(* Logix 5000 project; controller Electronic_Displays vendor 1 type 14 code 65 rev 17.4; software revision 17.01; part 5 of 9 *)
(* tags used below, declared in another part *)
   ENText2Message : BOOL;   // 0 = don't sent message 1 = send message
   ENText3Message : BOOL;   // 0 = don't sent message 1 = send message
   ENText4Message : BOOL;   // 0 = don't sent message 1 = send message
   ENTextFormats : BOOL;   // 0 = no additional text formatting 1 = enable text formatting
   ENVariable2Message : BOOL;   // 0 = don't sent embedded variable 1 = send embedded variable
   ENVariable3Message : BOOL;   // 0 = don't sent embedded variable 1 = send embedded variable
   ENVariable4Message : BOOL;   // 0 = don't sent embedded variable 1 = send embedded variable
   ENVariableFormats : BOOL;   // 0 = no additional text formatting 1 = enable text formatting
   SEQ : DINT;   // Sequence Number
   InCycle : BOOL;   // Incycle
   SignColor : STRING;
   SignFont : STRING;
   Packet : STRING[7];   // Packet Array to send to sign
   SignTextMessage4 : STRING;
   SignTextMessage3 : STRING;
   SignTextMessage2 : STRING;
   SignNextLine : STRING;   // DO NOT EDIT = ^M
   SignVariableFont : STRING;
   SignVariableColor : STRING;
   SignVariable3 : STRING;
   SignVariable2 : STRING;
   Select : DINT;   // Packet Array Select
   TotalPacketCount : DINT[7];   // Total Character Count
   PacketMax : DINT;   // Max Packet Count
   SignAttribute : STRING;
   SignVariableAttribute : STRING;
(* SendSignMessage, continued *)

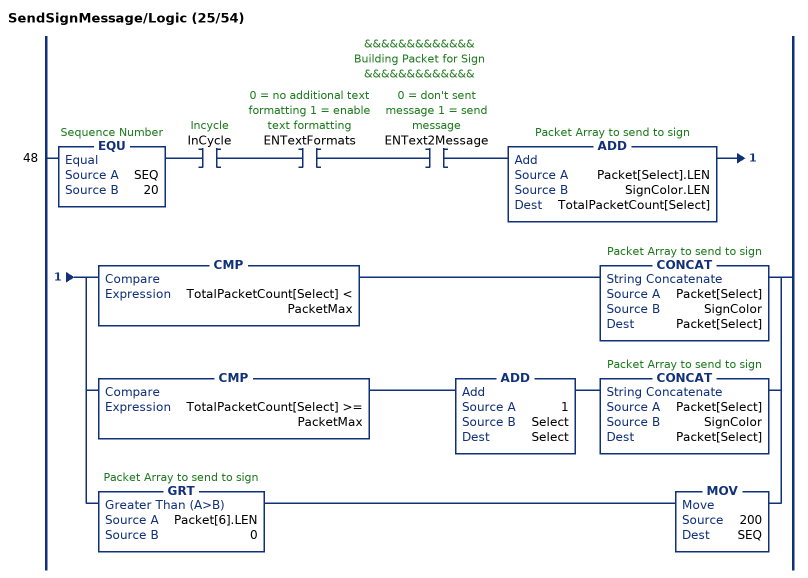
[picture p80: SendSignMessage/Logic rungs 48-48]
   // &&&&&&&&&&&&&
   // Building Packet for Sign
   // &&&&&&&&&&&&&
   48: EQU(SEQ,20)XIC(InCycle)XIC(ENTextFormats)XIC(ENText2Message)ADD(Packet[Select].LEN,SignColor.LEN,TotalPacketCount[Select])[CMP(TotalPacketCount[Select] < PacketMax) CONCAT(Packet[Select],SignColor,Packet[Select]) ,CMP(TotalPacketCount[Select] >= PacketMax) ADD(1,Select,Select) CONCAT(Packet[Select],SignColor,Packet[Select]) ,GRT(Packet[6].LEN,0) MOV(200,SEQ) ];
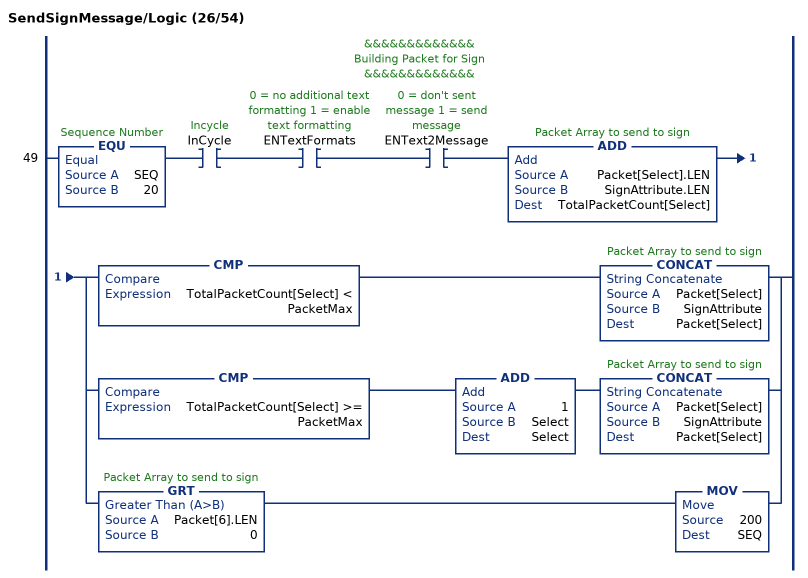
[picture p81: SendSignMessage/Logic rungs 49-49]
   // &&&&&&&&&&&&&
   // Building Packet for Sign
   // &&&&&&&&&&&&&
   49: EQU(SEQ,20)XIC(InCycle)XIC(ENTextFormats)XIC(ENText2Message)ADD(Packet[Select].LEN,SignAttribute.LEN,TotalPacketCount[Select])[CMP(TotalPacketCount[Select] < PacketMax) CONCAT(Packet[Select],SignAttribute,Packet[Select]) ,CMP(TotalPacketCount[Select] >= PacketMax) ADD(1,Select,Select) CONCAT(Packet[Select],SignAttribute,Packet[Select]) ,GRT(Packet[6].LEN,0) MOV(200,SEQ) ];
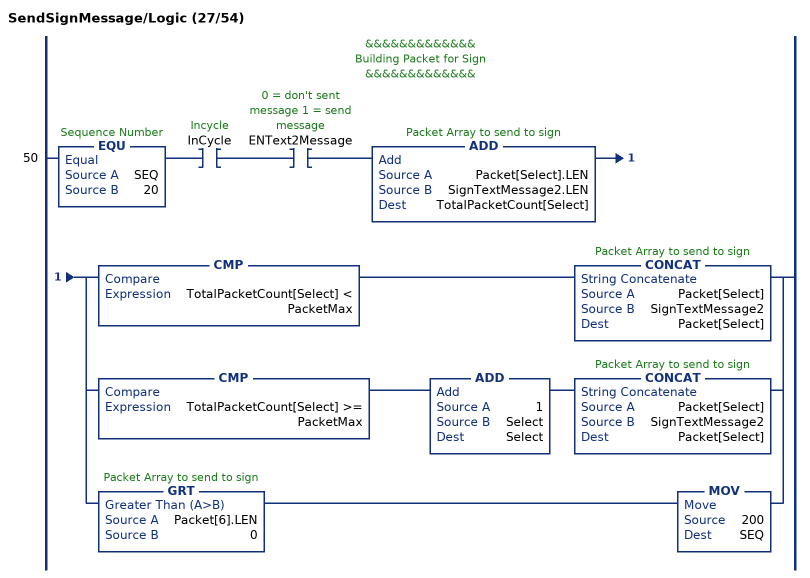
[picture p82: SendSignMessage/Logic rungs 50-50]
   // &&&&&&&&&&&&&
   // Building Packet for Sign
   // &&&&&&&&&&&&&
   50: EQU(SEQ,20)XIC(InCycle)XIC(ENText2Message)ADD(Packet[Select].LEN,SignTextMessage2.LEN,TotalPacketCount[Select])[CMP(TotalPacketCount[Select] < PacketMax) CONCAT(Packet[Select],SignTextMessage2,Packet[Select]) ,CMP(TotalPacketCount[Select] >= PacketMax) ADD(1,Select,Select) CONCAT(Packet[Select],SignTextMessage2,Packet[Select]) ,GRT(Packet[6].LEN,0) MOV(200,SEQ) ];
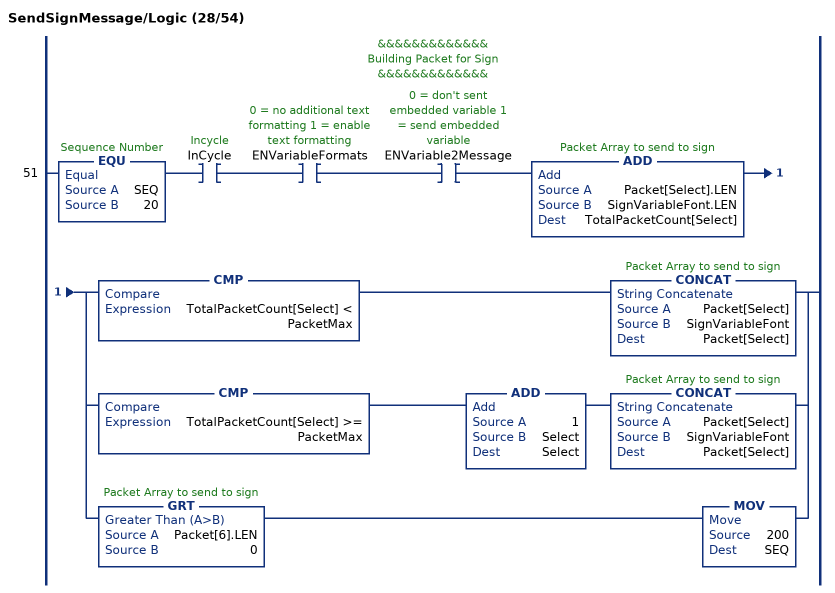
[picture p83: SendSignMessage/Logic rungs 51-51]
   // &&&&&&&&&&&&&
   // Building Packet for Sign
   // &&&&&&&&&&&&&
   51: EQU(SEQ,20)XIC(InCycle)XIC(ENVariableFormats)XIC(ENVariable2Message)ADD(Packet[Select].LEN,SignVariableFont.LEN,TotalPacketCount[Select])[CMP(TotalPacketCount[Select] < PacketMax) CONCAT(Packet[Select],SignVariableFont,Packet[Select]) ,CMP(TotalPacketCount[Select] >= PacketMax) ADD(1,Select,Select) CONCAT(Packet[Select],SignVariableFont,Packet[Select]) ,GRT(Packet[6].LEN,0) MOV(200,SEQ) ];
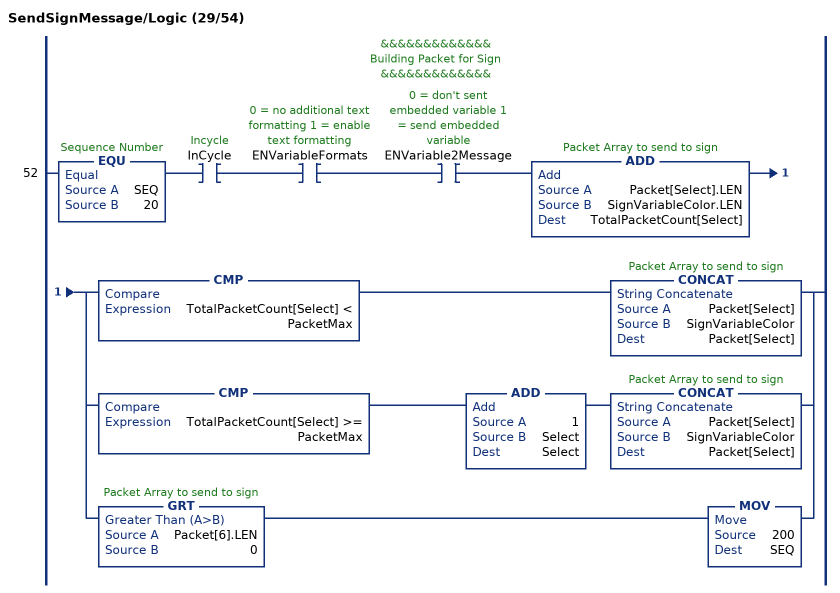
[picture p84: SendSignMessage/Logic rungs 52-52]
   // &&&&&&&&&&&&&
   // Building Packet for Sign
   // &&&&&&&&&&&&&
   52: EQU(SEQ,20)XIC(InCycle)XIC(ENVariableFormats)XIC(ENVariable2Message)ADD(Packet[Select].LEN,SignVariableColor.LEN,TotalPacketCount[Select])[CMP(TotalPacketCount[Select] < PacketMax) CONCAT(Packet[Select],SignVariableColor,Packet[Select]) ,CMP(TotalPacketCount[Select] >= PacketMax) ADD(1,Select,Select) CONCAT(Packet[Select],SignVariableColor,Packet[Select]) ,GRT(Packet[6].LEN,0) MOV(200,SEQ) ];
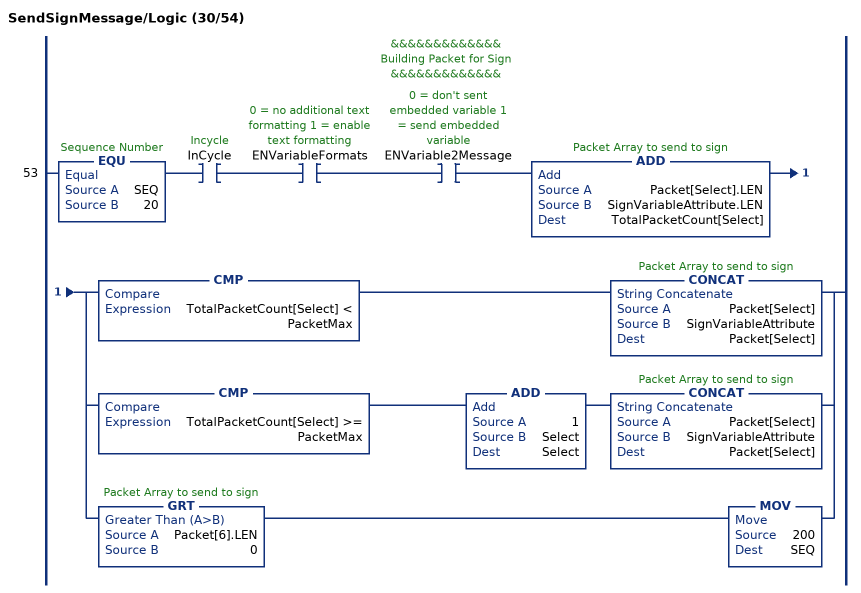
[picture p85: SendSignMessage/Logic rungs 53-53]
   // &&&&&&&&&&&&&
   // Building Packet for Sign
   // &&&&&&&&&&&&&
   53: EQU(SEQ,20)XIC(InCycle)XIC(ENVariableFormats)XIC(ENVariable2Message)ADD(Packet[Select].LEN,SignVariableAttribute.LEN,TotalPacketCount[Select])[CMP(TotalPacketCount[Select] < PacketMax) CONCAT(Packet[Select],SignVariableAttribute,Packet[Select]) ,CMP(TotalPacketCount[Select] >= PacketMax) ADD(1,Select,Select) CONCAT(Packet[Select],SignVariableAttribute,Packet[Select]) ,GRT(Packet[6].LEN,0) MOV(200,SEQ) ];
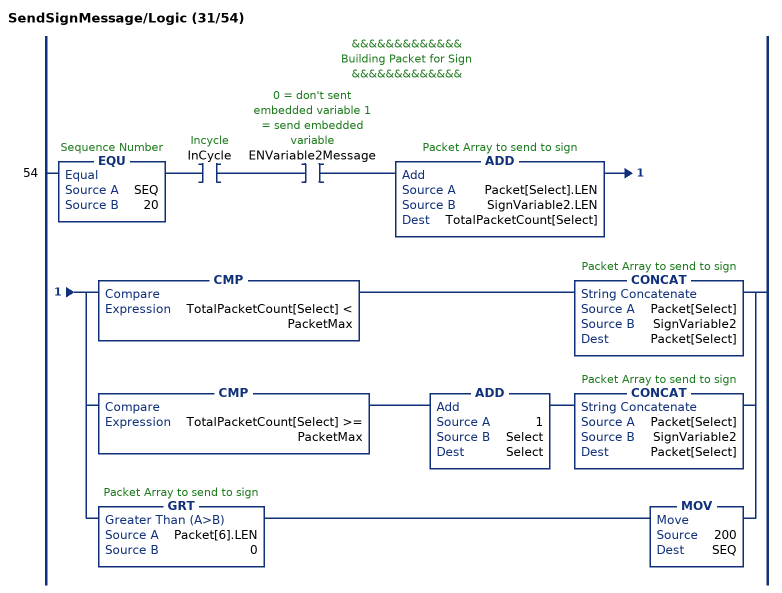
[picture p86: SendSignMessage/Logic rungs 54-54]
   // &&&&&&&&&&&&&
   // Building Packet for Sign
   // &&&&&&&&&&&&&
   54: EQU(SEQ,20)XIC(InCycle)XIC(ENVariable2Message)ADD(Packet[Select].LEN,SignVariable2.LEN,TotalPacketCount[Select])[CMP(TotalPacketCount[Select] < PacketMax) CONCAT(Packet[Select],SignVariable2,Packet[Select]) ,CMP(TotalPacketCount[Select] >= PacketMax) ADD(1,Select,Select) CONCAT(Packet[Select],SignVariable2,Packet[Select]) ,GRT(Packet[6].LEN,0) MOV(200,SEQ) ];
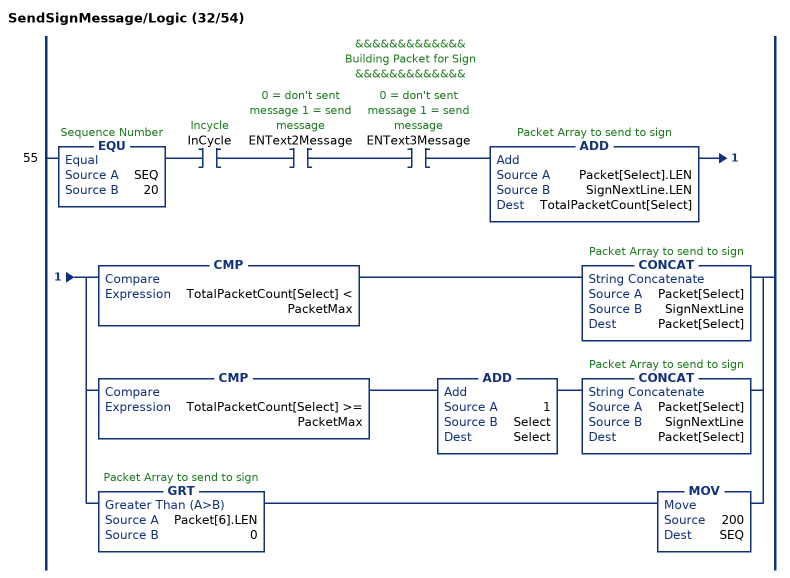
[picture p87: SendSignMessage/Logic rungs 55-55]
   // &&&&&&&&&&&&&
   // Building Packet for Sign
   // &&&&&&&&&&&&&
   55: EQU(SEQ,20)XIC(InCycle)XIC(ENText2Message)XIC(ENText3Message)ADD(Packet[Select].LEN,SignNextLine.LEN,TotalPacketCount[Select])[CMP(TotalPacketCount[Select] < PacketMax) CONCAT(Packet[Select],SignNextLine,Packet[Select]) ,CMP(TotalPacketCount[Select] >= PacketMax) ADD(1,Select,Select) CONCAT(Packet[Select],SignNextLine,Packet[Select]) ,GRT(Packet[6].LEN,0) MOV(200,SEQ) ];
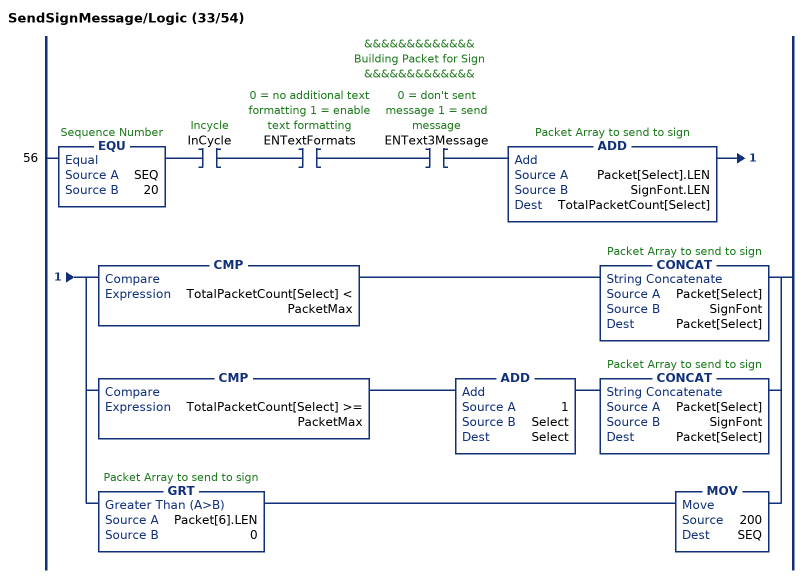
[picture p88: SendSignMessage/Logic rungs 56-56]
   // &&&&&&&&&&&&&
   // Building Packet for Sign
   // &&&&&&&&&&&&&
   56: EQU(SEQ,20)XIC(InCycle)XIC(ENTextFormats)XIC(ENText3Message)ADD(Packet[Select].LEN,SignFont.LEN,TotalPacketCount[Select])[CMP(TotalPacketCount[Select] < PacketMax) CONCAT(Packet[Select],SignFont,Packet[Select]) ,CMP(TotalPacketCount[Select] >= PacketMax) ADD(1,Select,Select) CONCAT(Packet[Select],SignFont,Packet[Select]) ,GRT(Packet[6].LEN,0) MOV(200,SEQ) ];
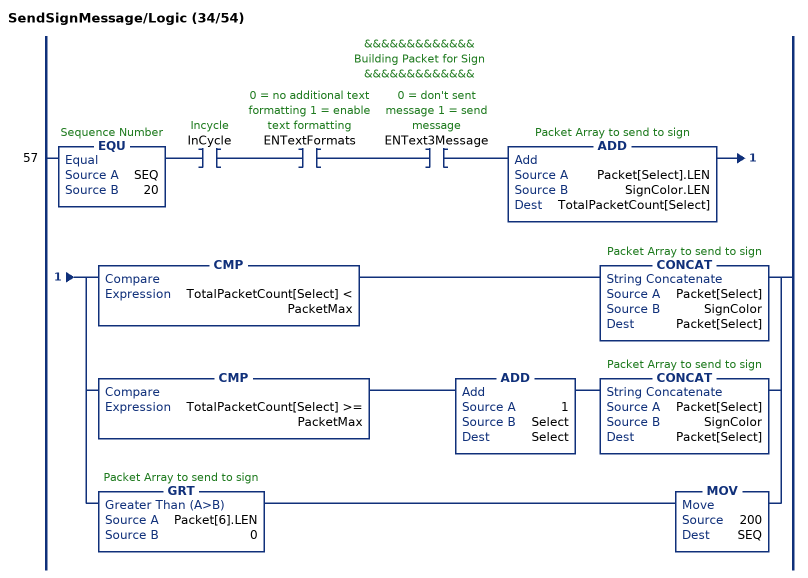
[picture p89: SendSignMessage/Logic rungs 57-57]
   // &&&&&&&&&&&&&
   // Building Packet for Sign
   // &&&&&&&&&&&&&
   57: EQU(SEQ,20)XIC(InCycle)XIC(ENTextFormats)XIC(ENText3Message)ADD(Packet[Select].LEN,SignColor.LEN,TotalPacketCount[Select])[CMP(TotalPacketCount[Select] < PacketMax) CONCAT(Packet[Select],SignColor,Packet[Select]) ,CMP(TotalPacketCount[Select] >= PacketMax) ADD(1,Select,Select) CONCAT(Packet[Select],SignColor,Packet[Select]) ,GRT(Packet[6].LEN,0) MOV(200,SEQ) ];
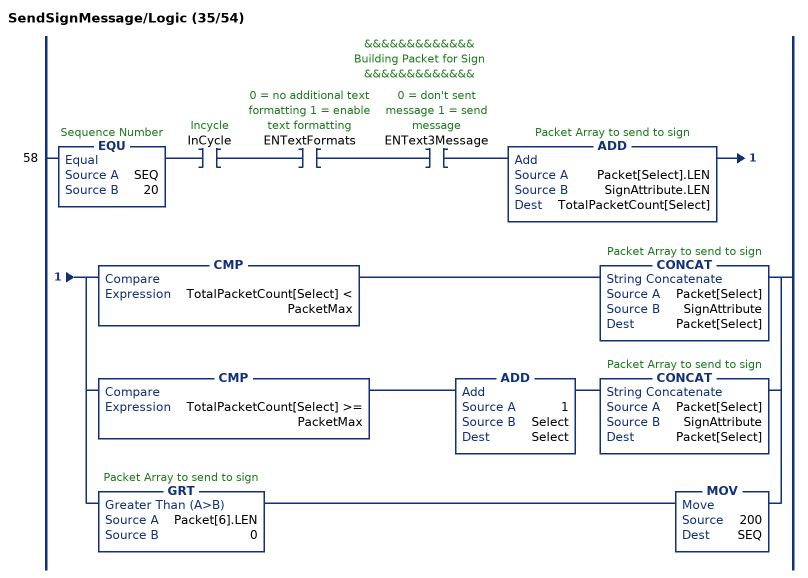
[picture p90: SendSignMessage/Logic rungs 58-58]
   // &&&&&&&&&&&&&
   // Building Packet for Sign
   // &&&&&&&&&&&&&
   58: EQU(SEQ,20)XIC(InCycle)XIC(ENTextFormats)XIC(ENText3Message)ADD(Packet[Select].LEN,SignAttribute.LEN,TotalPacketCount[Select])[CMP(TotalPacketCount[Select] < PacketMax) CONCAT(Packet[Select],SignAttribute,Packet[Select]) ,CMP(TotalPacketCount[Select] >= PacketMax) ADD(1,Select,Select) CONCAT(Packet[Select],SignAttribute,Packet[Select]) ,GRT(Packet[6].LEN,0) MOV(200,SEQ) ];
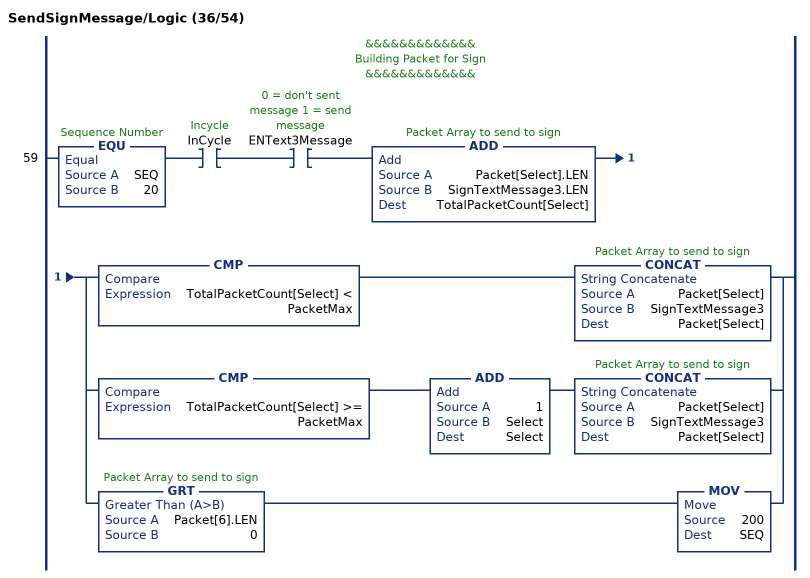
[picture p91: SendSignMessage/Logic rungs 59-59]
   // &&&&&&&&&&&&&
   // Building Packet for Sign
   // &&&&&&&&&&&&&
   59: EQU(SEQ,20)XIC(InCycle)XIC(ENText3Message)ADD(Packet[Select].LEN,SignTextMessage3.LEN,TotalPacketCount[Select])[CMP(TotalPacketCount[Select] < PacketMax) CONCAT(Packet[Select],SignTextMessage3,Packet[Select]) ,CMP(TotalPacketCount[Select] >= PacketMax) ADD(1,Select,Select) CONCAT(Packet[Select],SignTextMessage3,Packet[Select]) ,GRT(Packet[6].LEN,0) MOV(200,SEQ) ];
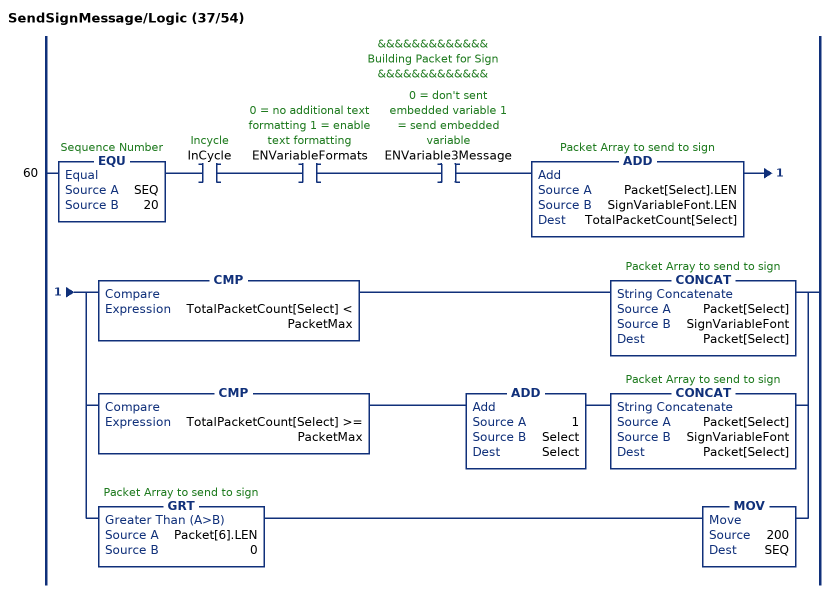
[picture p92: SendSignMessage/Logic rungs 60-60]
   // &&&&&&&&&&&&&
   // Building Packet for Sign
   // &&&&&&&&&&&&&
   60: EQU(SEQ,20)XIC(InCycle)XIC(ENVariableFormats)XIC(ENVariable3Message)ADD(Packet[Select].LEN,SignVariableFont.LEN,TotalPacketCount[Select])[CMP(TotalPacketCount[Select] < PacketMax) CONCAT(Packet[Select],SignVariableFont,Packet[Select]) ,CMP(TotalPacketCount[Select] >= PacketMax) ADD(1,Select,Select) CONCAT(Packet[Select],SignVariableFont,Packet[Select]) ,GRT(Packet[6].LEN,0) MOV(200,SEQ) ];
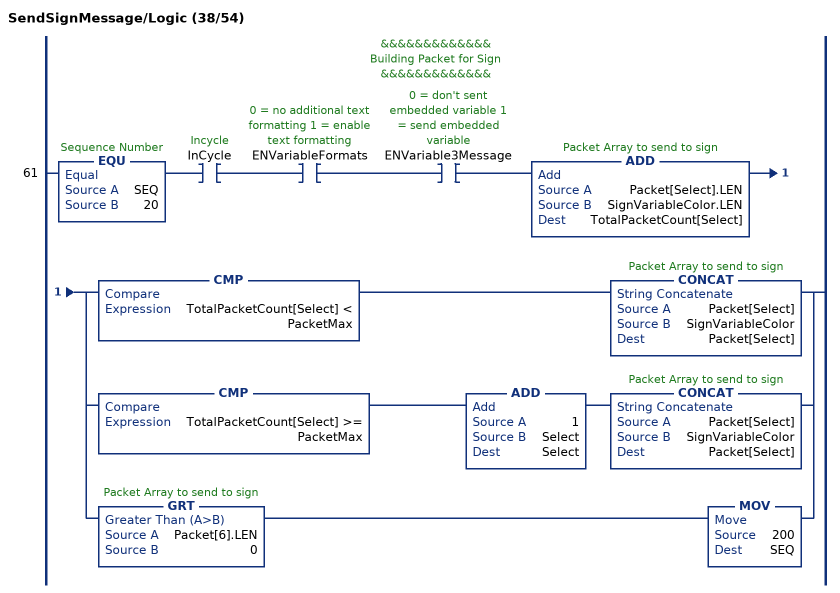
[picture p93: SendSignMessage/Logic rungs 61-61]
   // &&&&&&&&&&&&&
   // Building Packet for Sign
   // &&&&&&&&&&&&&
   61: EQU(SEQ,20)XIC(InCycle)XIC(ENVariableFormats)XIC(ENVariable3Message)ADD(Packet[Select].LEN,SignVariableColor.LEN,TotalPacketCount[Select])[CMP(TotalPacketCount[Select] < PacketMax) CONCAT(Packet[Select],SignVariableColor,Packet[Select]) ,CMP(TotalPacketCount[Select] >= PacketMax) ADD(1,Select,Select) CONCAT(Packet[Select],SignVariableColor,Packet[Select]) ,GRT(Packet[6].LEN,0) MOV(200,SEQ) ];
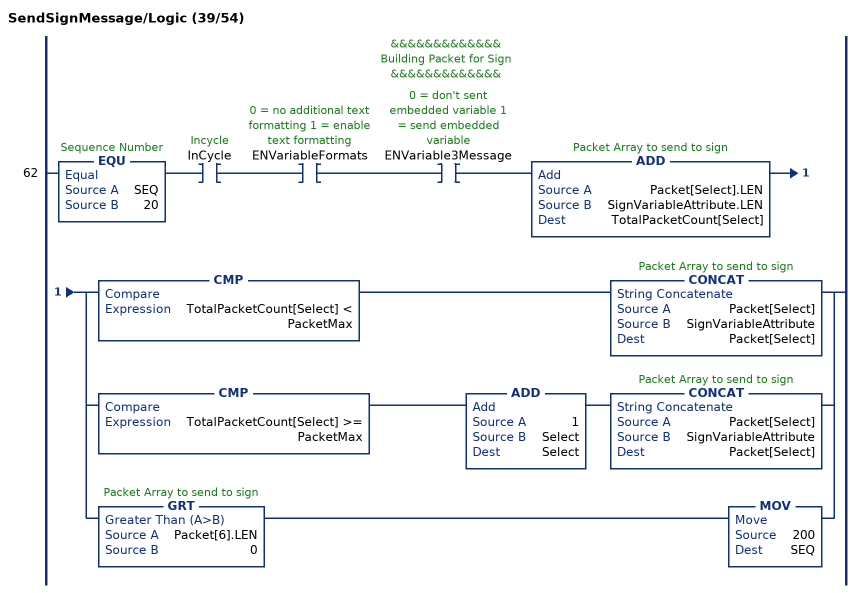
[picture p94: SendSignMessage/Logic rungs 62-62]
   // &&&&&&&&&&&&&
   // Building Packet for Sign
   // &&&&&&&&&&&&&
   62: EQU(SEQ,20)XIC(InCycle)XIC(ENVariableFormats)XIC(ENVariable3Message)ADD(Packet[Select].LEN,SignVariableAttribute.LEN,TotalPacketCount[Select])[CMP(TotalPacketCount[Select] < PacketMax) CONCAT(Packet[Select],SignVariableAttribute,Packet[Select]) ,CMP(TotalPacketCount[Select] >= PacketMax) ADD(1,Select,Select) CONCAT(Packet[Select],SignVariableAttribute,Packet[Select]) ,GRT(Packet[6].LEN,0) MOV(200,SEQ) ];
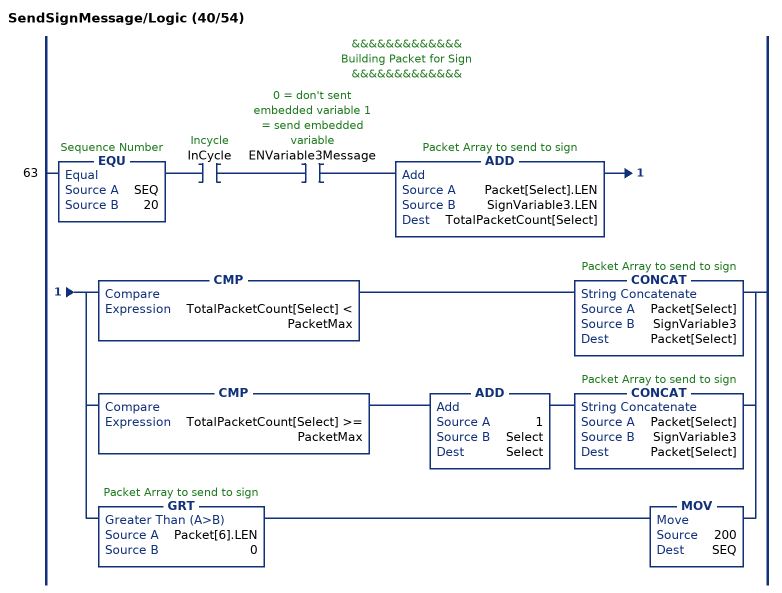
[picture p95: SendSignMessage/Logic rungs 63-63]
   // &&&&&&&&&&&&&
   // Building Packet for Sign
   // &&&&&&&&&&&&&
   63: EQU(SEQ,20)XIC(InCycle)XIC(ENVariable3Message)ADD(Packet[Select].LEN,SignVariable3.LEN,TotalPacketCount[Select])[CMP(TotalPacketCount[Select] < PacketMax) CONCAT(Packet[Select],SignVariable3,Packet[Select]) ,CMP(TotalPacketCount[Select] >= PacketMax) ADD(1,Select,Select) CONCAT(Packet[Select],SignVariable3,Packet[Select]) ,GRT(Packet[6].LEN,0) MOV(200,SEQ) ];
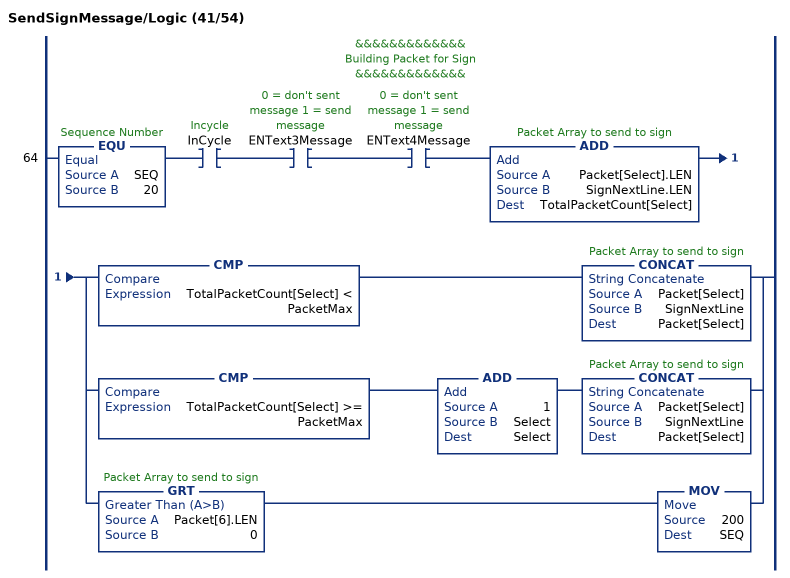
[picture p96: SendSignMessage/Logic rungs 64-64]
   // &&&&&&&&&&&&&
   // Building Packet for Sign
   // &&&&&&&&&&&&&
   64: EQU(SEQ,20)XIC(InCycle)XIC(ENText3Message)XIC(ENText4Message)ADD(Packet[Select].LEN,SignNextLine.LEN,TotalPacketCount[Select])[CMP(TotalPacketCount[Select] < PacketMax) CONCAT(Packet[Select],SignNextLine,Packet[Select]) ,CMP(TotalPacketCount[Select] >= PacketMax) ADD(1,Select,Select) CONCAT(Packet[Select],SignNextLine,Packet[Select]) ,GRT(Packet[6].LEN,0) MOV(200,SEQ) ];
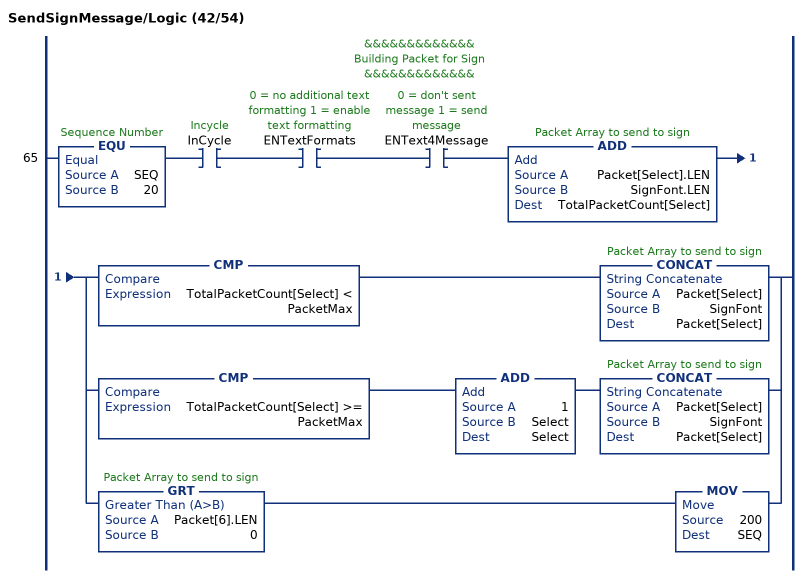
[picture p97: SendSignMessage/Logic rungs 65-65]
   // &&&&&&&&&&&&&
   // Building Packet for Sign
   // &&&&&&&&&&&&&
   65: EQU(SEQ,20)XIC(InCycle)XIC(ENTextFormats)XIC(ENText4Message)ADD(Packet[Select].LEN,SignFont.LEN,TotalPacketCount[Select])[CMP(TotalPacketCount[Select] < PacketMax) CONCAT(Packet[Select],SignFont,Packet[Select]) ,CMP(TotalPacketCount[Select] >= PacketMax) ADD(1,Select,Select) CONCAT(Packet[Select],SignFont,Packet[Select]) ,GRT(Packet[6].LEN,0) MOV(200,SEQ) ];
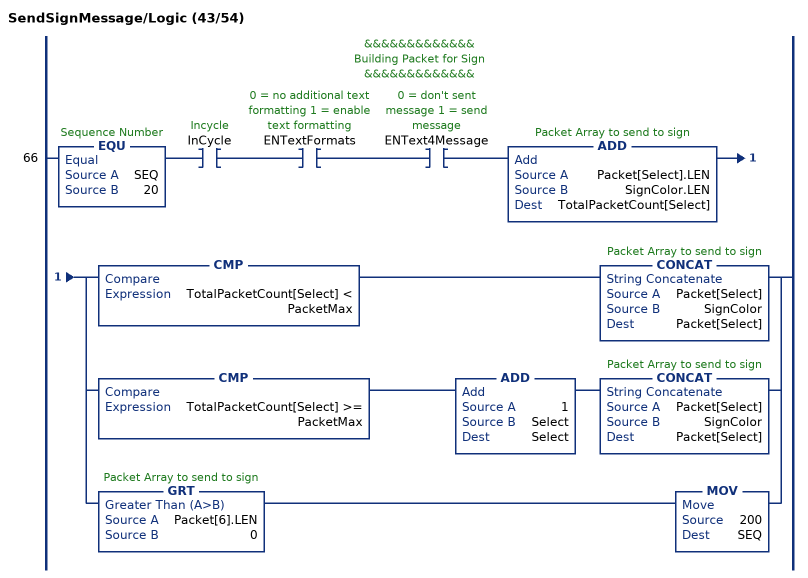
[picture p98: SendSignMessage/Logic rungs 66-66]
   // &&&&&&&&&&&&&
   // Building Packet for Sign
   // &&&&&&&&&&&&&
   66: EQU(SEQ,20)XIC(InCycle)XIC(ENTextFormats)XIC(ENText4Message)ADD(Packet[Select].LEN,SignColor.LEN,TotalPacketCount[Select])[CMP(TotalPacketCount[Select] < PacketMax) CONCAT(Packet[Select],SignColor,Packet[Select]) ,CMP(TotalPacketCount[Select] >= PacketMax) ADD(1,Select,Select) CONCAT(Packet[Select],SignColor,Packet[Select]) ,GRT(Packet[6].LEN,0) MOV(200,SEQ) ];
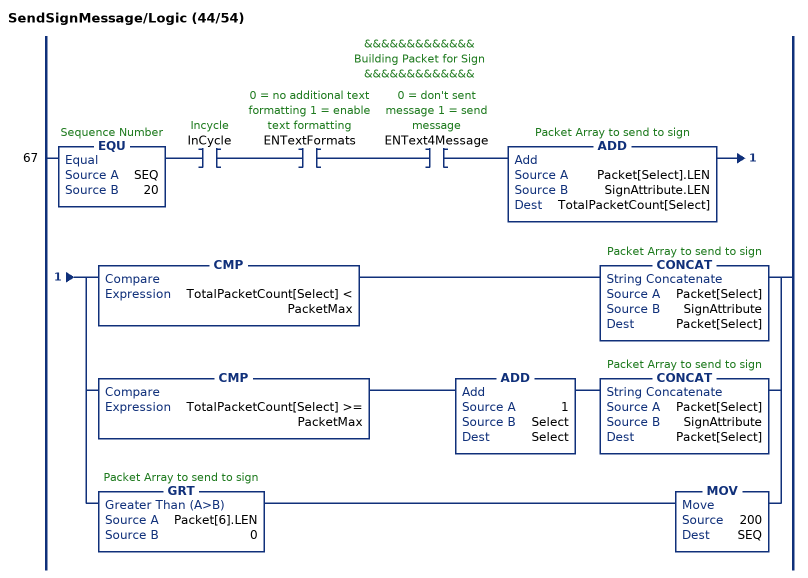
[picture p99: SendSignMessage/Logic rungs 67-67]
   // &&&&&&&&&&&&&
   // Building Packet for Sign
   // &&&&&&&&&&&&&
   67: EQU(SEQ,20)XIC(InCycle)XIC(ENTextFormats)XIC(ENText4Message)ADD(Packet[Select].LEN,SignAttribute.LEN,TotalPacketCount[Select])[CMP(TotalPacketCount[Select] < PacketMax) CONCAT(Packet[Select],SignAttribute,Packet[Select]) ,CMP(TotalPacketCount[Select] >= PacketMax) ADD(1,Select,Select) CONCAT(Packet[Select],SignAttribute,Packet[Select]) ,GRT(Packet[6].LEN,0) MOV(200,SEQ) ];
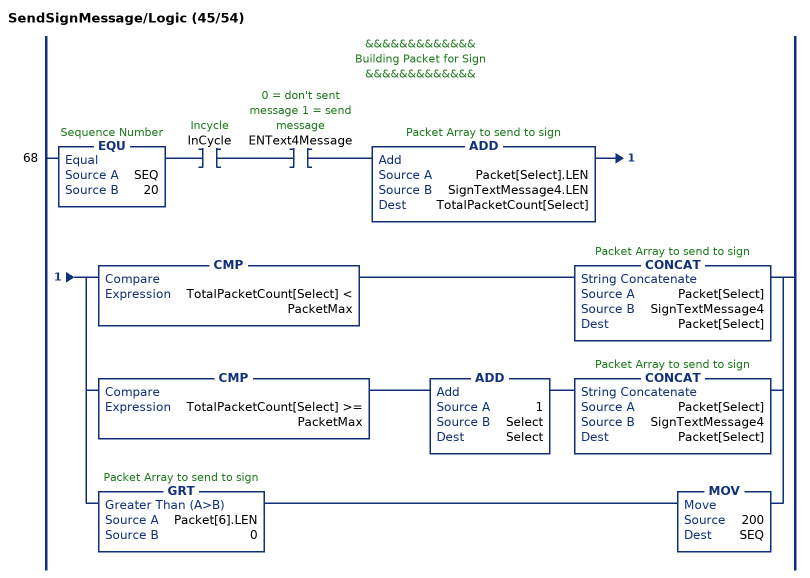
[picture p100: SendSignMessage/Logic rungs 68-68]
   // &&&&&&&&&&&&&
   // Building Packet for Sign
   // &&&&&&&&&&&&&
   68: EQU(SEQ,20)XIC(InCycle)XIC(ENText4Message)ADD(Packet[Select].LEN,SignTextMessage4.LEN,TotalPacketCount[Select])[CMP(TotalPacketCount[Select] < PacketMax) CONCAT(Packet[Select],SignTextMessage4,Packet[Select]) ,CMP(TotalPacketCount[Select] >= PacketMax) ADD(1,Select,Select) CONCAT(Packet[Select],SignTextMessage4,Packet[Select]) ,GRT(Packet[6].LEN,0) MOV(200,SEQ) ];
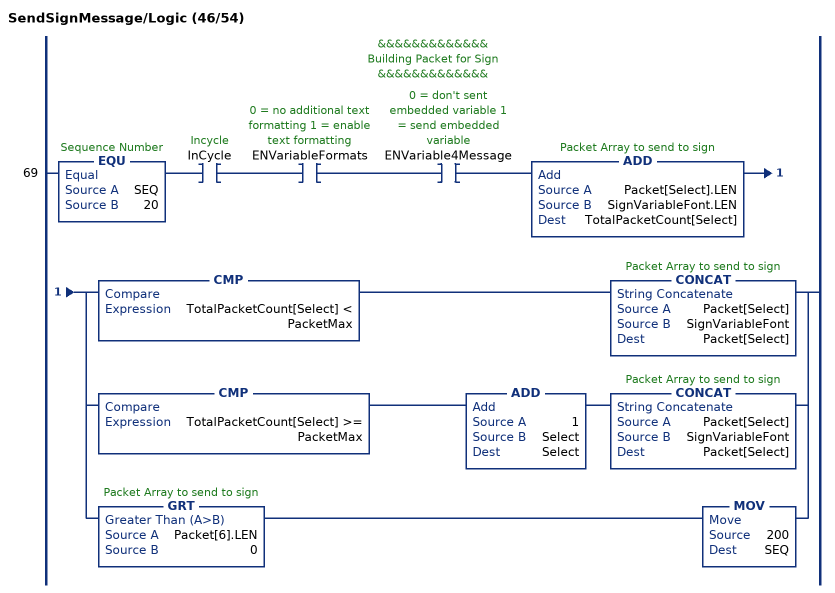
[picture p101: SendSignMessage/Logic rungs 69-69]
   // &&&&&&&&&&&&&
   // Building Packet for Sign
   // &&&&&&&&&&&&&
   69: EQU(SEQ,20)XIC(InCycle)XIC(ENVariableFormats)XIC(ENVariable4Message)ADD(Packet[Select].LEN,SignVariableFont.LEN,TotalPacketCount[Select])[CMP(TotalPacketCount[Select] < PacketMax) CONCAT(Packet[Select],SignVariableFont,Packet[Select]) ,CMP(TotalPacketCount[Select] >= PacketMax) ADD(1,Select,Select) CONCAT(Packet[Select],SignVariableFont,Packet[Select]) ,GRT(Packet[6].LEN,0) MOV(200,SEQ) ];
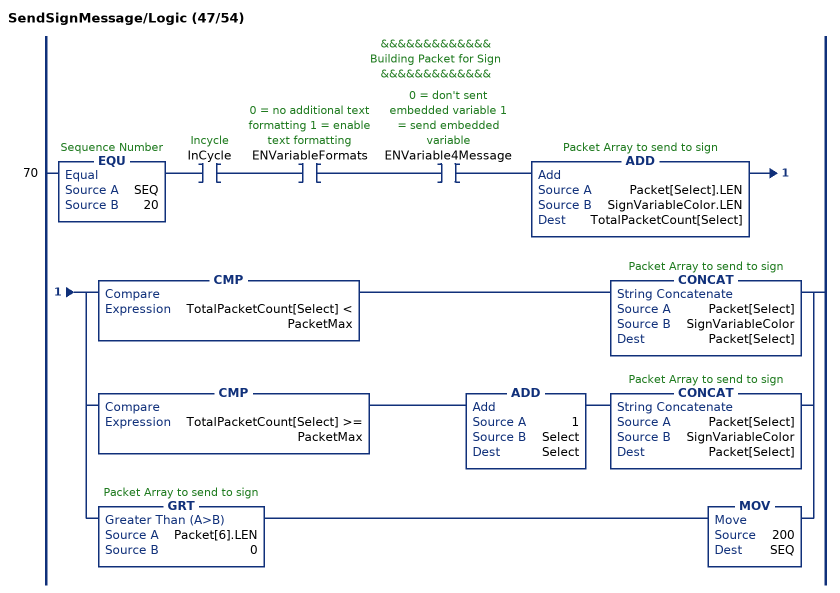
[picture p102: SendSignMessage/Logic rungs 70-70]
   // &&&&&&&&&&&&&
   // Building Packet for Sign
   // &&&&&&&&&&&&&
   70: EQU(SEQ,20)XIC(InCycle)XIC(ENVariableFormats)XIC(ENVariable4Message)ADD(Packet[Select].LEN,SignVariableColor.LEN,TotalPacketCount[Select])[CMP(TotalPacketCount[Select] < PacketMax) CONCAT(Packet[Select],SignVariableColor,Packet[Select]) ,CMP(TotalPacketCount[Select] >= PacketMax) ADD(1,Select,Select) CONCAT(Packet[Select],SignVariableColor,Packet[Select]) ,GRT(Packet[6].LEN,0) MOV(200,SEQ) ];
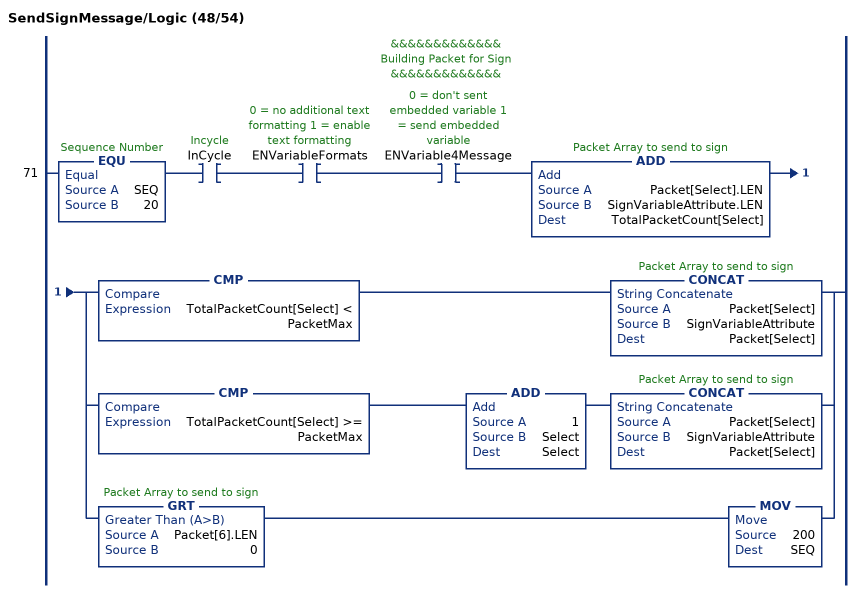
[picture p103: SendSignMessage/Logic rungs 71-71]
   // &&&&&&&&&&&&&
   // Building Packet for Sign
   // &&&&&&&&&&&&&
   71: EQU(SEQ,20)XIC(InCycle)XIC(ENVariableFormats)XIC(ENVariable4Message)ADD(Packet[Select].LEN,SignVariableAttribute.LEN,TotalPacketCount[Select])[CMP(TotalPacketCount[Select] < PacketMax) CONCAT(Packet[Select],SignVariableAttribute,Packet[Select]) ,CMP(TotalPacketCount[Select] >= PacketMax) ADD(1,Select,Select) CONCAT(Packet[Select],SignVariableAttribute,Packet[Select]) ,GRT(Packet[6].LEN,0) MOV(200,SEQ) ];
